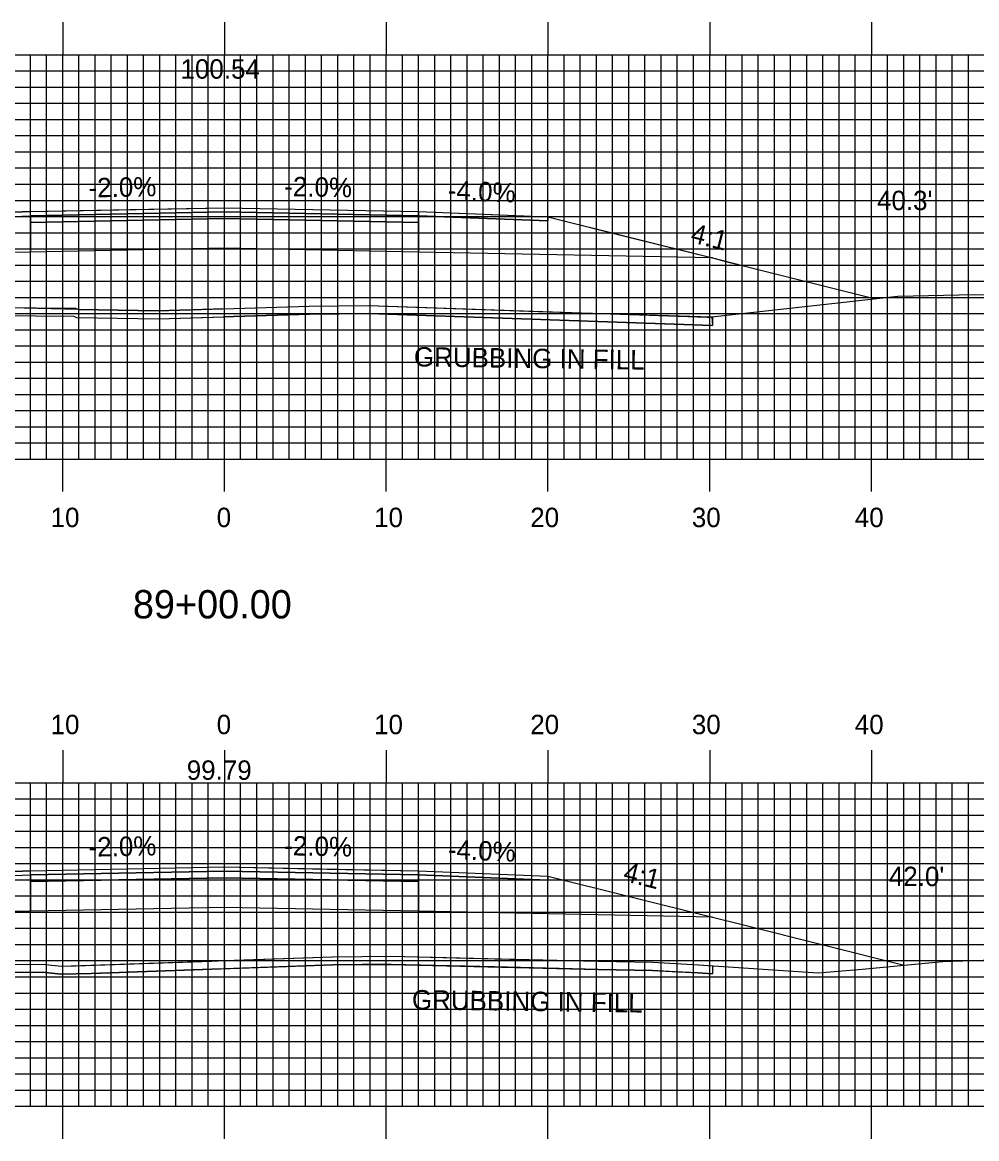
# Model space of a CAD drawing. Extents: x 1764152 to 1764495, y 442591 to 442811.
# Drawn here: x 1764305.3 to 1764364.3, y 442686.7 to 442755.7 of the extents above; entities that cross this region are included whole.
import ezdxf

# ---------------------------------------------------------------- set-up
doc = ezdxf.new("R2010")
doc.units = 0
for name, color, linetype in [('ANNOTATION', 7, 'Continuous'), ('D_Roadway_Centerline', 7, 'Continuous'), ('D_Roadway_Centerline_Text', 7, 'Continuous'), ('D_Roadway_Edge_Shoulder', 7, 'Continuous'), ('D_Roadway_Edge_TW', 7, 'Continuous'), ('D_Roadway_Pavement', 7, 'Continuous'), ('D_Roadway_SlopeLines', 7, 'Continuous'), ('D_Roadway_SubGrade', 7, 'Continuous'), ('D_Text_Standard', 7, 'Continuous'), ('GRUBBING IN FILL', 7, 'Continuous'), ('H_V ANNOTATION', 7, 'Continuous'), ('MAJOR', 7, 'Continuous'), ('MINOR', 7, 'Continuous'), ('S_Roadway_Centerline', 7, 'Continuous')]:
    doc.layers.add(name, color=color, linetype=linetype)

msp = doc.modelspace()

# ---------------------------------------------------------------- linework, layer by layer
at = {"layer": 'D_Roadway_Centerline'}
for points in [[(1764297.833, 442743.646), (1764305.832, 442743.966), (1764305.837, 442743.966), (1764311.976, 442744.089), (1764317.827, 442744.206), (1764317.832, 442744.206), (1764329.827, 442743.966), (1764329.832, 442743.966), (1764334.355, 442743.785), (1764337.829, 442743.646), (1764337.831, 442743.646), (1764343.157, 442742.315), (1764348.003, 442741.103), (1764348.006, 442741.102), (1764348.84, 442740.894), (1764349.832, 442740.646), (1764349.834, 442740.646), (1764358.085, 442738.582)], [(1764279.726, 442698.369), (1764287.655, 442700.352), (1764287.658, 442700.352), (1764297.83, 442702.896), (1764297.831, 442702.896), (1764305.828, 442703.216), (1764305.832, 442703.216), (1764305.837, 442703.216), (1764317.832, 442703.456), (1764317.837, 442703.456), (1764324.189, 442703.329), (1764329.827, 442703.216), (1764329.832, 442703.216), (1764337.832, 442702.896), (1764348.003, 442700.353), (1764348.006, 442700.352), (1764349.832, 442699.896), (1764359.855, 442697.39), (1764359.858, 442697.389)]]:
    msp.add_lwpolyline(points, dxfattribs=at)
at = {"layer": 'D_Roadway_Edge_Shoulder'}
for points in [[(1764305.832, 442743.966), (1764297.832, 442743.646), (1764297.832, 442743.396), (1764305.832, 442743.716)], [(1764329.832, 442743.966), (1764337.831, 442743.646), (1764337.831, 442743.396), (1764329.832, 442743.716)], [(1764305.832, 442703.216), (1764297.831, 442702.896), (1764297.831, 442702.646), (1764305.832, 442702.966)], [(1764329.832, 442703.216), (1764337.832, 442702.896), (1764337.832, 442702.646), (1764329.832, 442702.966)]]:
    msp.add_lwpolyline(points, close=True, dxfattribs=at)
at = {"layer": 'D_Roadway_Edge_TW'}
for points in [[(1764305.832, 442743.716), (1764305.832, 442743.966), (1764317.832, 442744.206), (1764329.832, 442743.966), (1764329.832, 442743.716), (1764317.832, 442743.956)], [(1764329.832, 442743.966), (1764329.832, 442743.966), (1764329.832, 442743.716), (1764329.832, 442743.716)], [(1764305.832, 442702.966), (1764305.832, 442703.216), (1764317.832, 442703.456), (1764329.832, 442703.216), (1764329.832, 442702.966), (1764317.832, 442703.206)], [(1764329.832, 442703.216), (1764329.832, 442703.216), (1764329.832, 442702.966), (1764329.832, 442702.966)]]:
    msp.add_lwpolyline(points, close=True, dxfattribs=at)
at = {"layer": 'D_Roadway_Pavement'}
for points in [[(1764305.832, 442743.299), (1764305.832, 442743.716), (1764317.832, 442743.956), (1764329.832, 442743.716), (1764329.832, 442743.299), (1764317.832, 442743.539)], [(1764329.832, 442743.716), (1764329.832, 442743.716), (1764329.832, 442743.299), (1764329.832, 442743.299)], [(1764305.832, 442702.549), (1764305.832, 442702.966), (1764317.832, 442703.206), (1764329.832, 442702.966), (1764329.832, 442702.549), (1764317.832, 442702.789)], [(1764329.832, 442702.966), (1764329.832, 442702.966), (1764329.832, 442702.549), (1764329.832, 442702.549)]]:
    msp.add_lwpolyline(points, close=True, dxfattribs=at)
for points in [[(1764329.832, 442743.716), (1764329.832, 442743.299)], [(1764329.832, 442743.716), (1764329.832, 442743.299)], [(1764329.832, 442743.716), (1764329.832, 442743.299)], [(1764329.832, 442702.966), (1764329.832, 442702.549)], [(1764329.832, 442702.966), (1764329.832, 442702.549)], [(1764329.832, 442702.966), (1764329.832, 442702.549)]]:
    msp.add_lwpolyline(points, dxfattribs=at)
at = {"layer": 'D_Roadway_SlopeLines'}
for points in [[(1764337.831, 442743.646), (1764348.006, 442741.102), (1764349.832, 442740.646), (1764358.085, 442738.582)], [(1764337.832, 442702.896), (1764348.005, 442700.352), (1764349.832, 442699.896), (1764359.858, 442697.389)]]:
    msp.add_lwpolyline(points, dxfattribs=at)
at = {"layer": 'D_Roadway_SubGrade'}
for points in [[(1764297.832, 442743.396), (1764305.832, 442743.716), (1764305.832, 442743.299), (1764305.832, 442741.466), (1764287.658, 442741.102), (1764297.832, 442743.646)], [(1764329.832, 442743.299), (1764329.832, 442743.716), (1764337.831, 442743.396), (1764337.831, 442743.646), (1764348.006, 442741.102), (1764329.832, 442741.466)], [(1764305.832, 442741.466), (1764305.832, 442743.299), (1764317.832, 442743.539), (1764329.832, 442743.299), (1764329.832, 442741.466), (1764317.832, 442741.706)], [(1764329.832, 442743.299), (1764329.832, 442743.299), (1764329.832, 442741.466), (1764329.832, 442741.466)], [(1764297.831, 442702.646), (1764305.832, 442702.966), (1764305.832, 442702.549), (1764305.832, 442700.716), (1764287.658, 442700.352), (1764297.831, 442702.896)], [(1764329.832, 442702.549), (1764329.832, 442702.966), (1764337.832, 442702.646), (1764337.832, 442702.896), (1764348.005, 442700.352), (1764329.832, 442700.716)], [(1764305.832, 442700.716), (1764305.832, 442702.549), (1764317.832, 442702.789), (1764329.832, 442702.549), (1764329.832, 442700.716), (1764317.832, 442700.956)], [(1764329.832, 442702.549), (1764329.832, 442702.549), (1764329.832, 442700.716), (1764329.832, 442700.716)]]:
    msp.add_lwpolyline(points, close=True, dxfattribs=at)
at = {"layer": 'GRUBBING IN FILL'}
for p, q in [((1764348.006, 442737.462), (1764348.006, 442736.93)), ((1764348.005, 442697.347), (1764348.005, 442696.846))]:
    msp.add_line(p, q, dxfattribs=at)
for points in [[(1764287.658, 442738.108), (1764289.607, 442738.031), (1764291.566, 442737.976), (1764297.792, 442737.756), (1764301.124, 442737.61), (1764301.59, 442737.589), (1764301.948, 442737.581), (1764303.753, 442737.543), (1764308.512, 442737.499), (1764308.687, 442737.428), (1764313.742, 442737.34), (1764317.832, 442737.463), (1764317.832, 442737.963), (1764313.739, 442737.84), (1764311.264, 442737.883), (1764308.789, 442737.926), (1764303.761, 442738.043), (1764293.972, 442738.424), (1764289.795, 442738.524), (1764287.658, 442738.609)], [(1764287.658, 442738.108), (1764289.607, 442738.031), (1764291.566, 442737.976), (1764297.792, 442737.756), (1764301.124, 442737.61), (1764301.59, 442737.589), (1764301.948, 442737.581), (1764303.753, 442737.543), (1764308.512, 442737.499), (1764308.687, 442737.428), (1764313.742, 442737.34), (1764317.832, 442737.463), (1764317.832, 442737.963), (1764313.739, 442737.84), (1764311.264, 442737.883), (1764308.789, 442737.926), (1764303.761, 442738.043), (1764293.972, 442738.424), (1764289.795, 442738.524), (1764287.658, 442738.609)], [(1764317.832, 442737.963), (1764318.404, 442737.981), (1764323.069, 442738.121), (1764326.754, 442738.164), (1764337.219, 442737.803), (1764347.961, 442737.457), (1764348.006, 442736.93), (1764337.377, 442737.297), (1764326.748, 442737.664), (1764324.914, 442737.642), (1764323.079, 442737.621), (1764318.411, 442737.481), (1764317.832, 442737.463)], [(1764317.832, 442737.963), (1764318.404, 442737.981), (1764323.069, 442738.121), (1764326.754, 442738.164), (1764337.219, 442737.803), (1764347.961, 442737.457), (1764348.006, 442736.93), (1764337.377, 442737.297), (1764326.748, 442737.664), (1764324.914, 442737.642), (1764323.079, 442737.621), (1764318.411, 442737.481), (1764317.832, 442737.463)], [(1764287.658, 442698.001), (1764291.965, 442697.77), (1764294.549, 442697.523), (1764297.109, 442697.506), (1764301.952, 442697.466), (1764306.795, 442697.426), (1764307.73, 442697.326), (1764308.647, 442697.353), (1764317.043, 442697.642), (1764317.832, 442697.669), (1764317.832, 442697.169), (1764317.056, 442697.142), (1764309.581, 442696.88), (1764307.711, 442696.825), (1764306.767, 442696.926), (1764301.937, 442696.966), (1764297.107, 442697.006), (1764294.9, 442697.009), (1764294.518, 442697.024), (1764294.342, 442697.036), (1764291.927, 442697.271), (1764287.658, 442697.5)], [(1764287.658, 442698.001), (1764291.965, 442697.77), (1764294.549, 442697.523), (1764297.109, 442697.506), (1764301.952, 442697.466), (1764306.795, 442697.426), (1764307.73, 442697.326), (1764308.647, 442697.353), (1764317.043, 442697.642), (1764317.832, 442697.669), (1764317.832, 442697.169), (1764317.056, 442697.142), (1764309.581, 442696.88), (1764307.711, 442696.825), (1764306.767, 442696.926), (1764301.937, 442696.966), (1764297.107, 442697.006), (1764294.9, 442697.009), (1764294.518, 442697.024), (1764294.342, 442697.036), (1764291.927, 442697.271), (1764287.658, 442697.5)], [(1764317.832, 442697.669), (1764324.52, 442697.904), (1764328.147, 442697.934), (1764334.545, 442697.781), (1764340.943, 442697.629), (1764344.313, 442697.563), (1764347.15, 442697.404), (1764348.005, 442697.347), (1764348.005, 442696.846), (1764347.119, 442696.905), (1764345.707, 442696.984), (1764344.294, 442697.063), (1764340.932, 442697.129), (1764334.537, 442697.281), (1764328.143, 442697.434), (1764326.337, 442697.419), (1764324.531, 442697.404), (1764317.832, 442697.169)], [(1764317.832, 442697.669), (1764324.52, 442697.904), (1764328.147, 442697.934), (1764334.545, 442697.781), (1764340.943, 442697.629), (1764344.313, 442697.563), (1764347.15, 442697.404), (1764348.005, 442697.347), (1764348.005, 442696.846), (1764347.119, 442696.905), (1764345.707, 442696.984), (1764344.294, 442697.063), (1764340.932, 442697.129), (1764334.537, 442697.281), (1764328.143, 442697.434), (1764326.337, 442697.419), (1764324.531, 442697.404), (1764317.832, 442697.169)]]:
    msp.add_lwpolyline(points, close=True, dxfattribs=at)
for points in [[(1764287.658, 442738.108), (1764289.779, 442738.024), (1764293.354, 442737.927), (1764293.959, 442737.924), (1764301.624, 442737.588), (1764303.753, 442737.543), (1764308.512, 442737.499), (1764308.687, 442737.428), (1764313.742, 442737.34), (1764323.079, 442737.621), (1764326.748, 442737.664), (1764348.006, 442736.93)], [(1764287.658, 442697.5), (1764291.927, 442697.271), (1764294.342, 442697.036), (1764294.693, 442697.013), (1764295.106, 442697.004), (1764297.107, 442697.006), (1764306.767, 442696.926), (1764307.711, 442696.825), (1764309.581, 442696.88), (1764324.531, 442697.404), (1764328.143, 442697.434), (1764340.932, 442697.129), (1764344.294, 442697.063), (1764347.119, 442696.905), (1764348.005, 442696.846)]]:
    msp.add_lwpolyline(points, dxfattribs=at)
at = {"layer": 'MAJOR'}
for p, q in [((1764307.832, 442755.669), (1764307.832, 442753.665)), ((1764317.832, 442755.669), (1764317.832, 442753.665)), ((1764327.832, 442755.669), (1764327.832, 442753.665)), ((1764337.832, 442755.669), (1764337.832, 442753.665)), ((1764347.832, 442755.669), (1764347.832, 442753.665)), ((1764357.832, 442755.669), (1764357.832, 442753.665)), ((1764177.832, 442753.665), (1764457.832, 442753.665)), ((1764177.832, 442753.665), (1764457.832, 442753.665)), ((1764307.832, 442728.665), (1764307.832, 442753.665)), ((1764317.832, 442728.665), (1764317.832, 442753.665)), ((1764327.832, 442728.665), (1764327.832, 442753.665)), ((1764337.832, 442728.665), (1764337.832, 442753.665)), ((1764347.832, 442728.665), (1764347.832, 442753.665)), ((1764357.832, 442728.665), (1764357.832, 442753.665)), ((1764177.832, 442748.665), (1764457.832, 442748.665)), ((1764177.832, 442743.665), (1764457.832, 442743.665)), ((1764177.832, 442738.665), (1764457.832, 442738.665)), ((1764177.832, 442733.665), (1764457.832, 442733.665)), ((1764177.832, 442728.665), (1764457.832, 442728.665)), ((1764177.832, 442728.665), (1764457.832, 442728.665)), ((1764307.832, 442726.661), (1764307.832, 442728.665)), ((1764317.832, 442726.661), (1764317.832, 442728.665)), ((1764327.832, 442726.661), (1764327.832, 442728.665)), ((1764337.832, 442726.661), (1764337.832, 442728.665)), ((1764347.832, 442726.661), (1764347.832, 442728.665)), ((1764357.832, 442726.661), (1764357.832, 442728.665)), ((1764307.832, 442710.669), (1764307.832, 442708.665)), ((1764317.832, 442710.669), (1764317.832, 442708.665)), ((1764327.832, 442710.669), (1764327.832, 442708.665)), ((1764337.832, 442710.669), (1764337.832, 442708.665)), ((1764347.832, 442710.669), (1764347.832, 442708.665)), ((1764357.832, 442710.669), (1764357.832, 442708.665)), ((1764177.832, 442708.665), (1764457.832, 442708.665)), ((1764177.832, 442708.665), (1764457.832, 442708.665)), ((1764307.832, 442688.665), (1764307.832, 442708.665)), ((1764317.832, 442688.665), (1764317.832, 442708.665)), ((1764327.832, 442688.665), (1764327.832, 442708.665)), ((1764337.832, 442688.665), (1764337.832, 442708.665)), ((1764347.832, 442688.665), (1764347.832, 442708.665)), ((1764357.832, 442688.665), (1764357.832, 442708.665)), ((1764177.832, 442703.665), (1764457.832, 442703.665)), ((1764177.832, 442698.665), (1764457.832, 442698.665)), ((1764177.832, 442693.665), (1764457.832, 442693.665)), ((1764177.832, 442688.665), (1764457.832, 442688.665)), ((1764177.832, 442688.665), (1764457.832, 442688.665)), ((1764307.832, 442686.661), (1764307.832, 442688.665)), ((1764317.832, 442686.661), (1764317.832, 442688.665)), ((1764327.832, 442686.661), (1764327.832, 442688.665)), ((1764337.832, 442686.661), (1764337.832, 442688.665)), ((1764347.832, 442686.661), (1764347.832, 442688.665)), ((1764357.832, 442686.661), (1764357.832, 442688.665))]:
    msp.add_line(p, q, dxfattribs=at)
at = {"layer": 'MINOR'}
for p, q in [((1764305.832, 442728.665), (1764305.832, 442753.665)), ((1764306.832, 442728.665), (1764306.832, 442753.665)), ((1764308.832, 442728.665), (1764308.832, 442753.665)), ((1764309.832, 442728.665), (1764309.832, 442753.665)), ((1764310.832, 442728.665), (1764310.832, 442753.665)), ((1764311.832, 442728.665), (1764311.832, 442753.665)), ((1764312.832, 442728.665), (1764312.832, 442753.665)), ((1764313.832, 442728.665), (1764313.832, 442753.665)), ((1764314.832, 442728.665), (1764314.832, 442753.665)), ((1764315.832, 442728.665), (1764315.832, 442753.665)), ((1764316.832, 442728.665), (1764316.832, 442753.665)), ((1764318.832, 442728.665), (1764318.832, 442753.665)), ((1764319.832, 442728.665), (1764319.832, 442753.665)), ((1764320.832, 442728.665), (1764320.832, 442753.665)), ((1764321.832, 442728.665), (1764321.832, 442753.665)), ((1764322.832, 442728.665), (1764322.832, 442753.665)), ((1764323.832, 442728.665), (1764323.832, 442753.665)), ((1764324.832, 442728.665), (1764324.832, 442753.665)), ((1764325.832, 442728.665), (1764325.832, 442753.665)), ((1764326.832, 442728.665), (1764326.832, 442753.665)), ((1764328.832, 442728.665), (1764328.832, 442753.665)), ((1764329.832, 442728.665), (1764329.832, 442753.665)), ((1764330.832, 442728.665), (1764330.832, 442753.665)), ((1764331.832, 442728.665), (1764331.832, 442753.665)), ((1764332.832, 442728.665), (1764332.832, 442753.665)), ((1764333.832, 442728.665), (1764333.832, 442753.665)), ((1764334.832, 442728.665), (1764334.832, 442753.665)), ((1764335.832, 442728.665), (1764335.832, 442753.665)), ((1764336.832, 442728.665), (1764336.832, 442753.665)), ((1764338.832, 442728.665), (1764338.832, 442753.665)), ((1764339.832, 442728.665), (1764339.832, 442753.665)), ((1764340.832, 442728.665), (1764340.832, 442753.665)), ((1764341.832, 442728.665), (1764341.832, 442753.665)), ((1764342.832, 442728.665), (1764342.832, 442753.665)), ((1764343.832, 442728.665), (1764343.832, 442753.665)), ((1764344.832, 442728.665), (1764344.832, 442753.665)), ((1764345.832, 442728.665), (1764345.832, 442753.665)), ((1764346.832, 442728.665), (1764346.832, 442753.665)), ((1764348.832, 442728.665), (1764348.832, 442753.665)), ((1764349.832, 442728.665), (1764349.832, 442753.665)), ((1764350.832, 442728.665), (1764350.832, 442753.665)), ((1764351.832, 442728.665), (1764351.832, 442753.665)), ((1764352.832, 442728.665), (1764352.832, 442753.665)), ((1764353.832, 442728.665), (1764353.832, 442753.665)), ((1764354.832, 442728.665), (1764354.832, 442753.665)), ((1764355.832, 442728.665), (1764355.832, 442753.665)), ((1764356.832, 442728.665), (1764356.832, 442753.665)), ((1764358.832, 442728.665), (1764358.832, 442753.665)), ((1764359.832, 442728.665), (1764359.832, 442753.665)), ((1764360.832, 442728.665), (1764360.832, 442753.665)), ((1764361.832, 442728.665), (1764361.832, 442753.665)), ((1764362.832, 442728.665), (1764362.832, 442753.665)), ((1764363.832, 442728.665), (1764363.832, 442753.665)), ((1764177.832, 442752.665), (1764457.832, 442752.665)), ((1764177.832, 442751.665), (1764457.832, 442751.665)), ((1764177.832, 442750.665), (1764457.832, 442750.665)), ((1764177.832, 442749.665), (1764457.832, 442749.665)), ((1764177.832, 442747.665), (1764457.832, 442747.665)), ((1764177.832, 442746.665), (1764457.832, 442746.665)), ((1764177.832, 442745.665), (1764457.832, 442745.665)), ((1764177.832, 442744.665), (1764457.832, 442744.665)), ((1764177.832, 442742.665), (1764457.832, 442742.665)), ((1764177.832, 442741.665), (1764457.832, 442741.665)), ((1764177.832, 442740.665), (1764457.832, 442740.665)), ((1764177.832, 442739.665), (1764457.832, 442739.665)), ((1764177.832, 442737.665), (1764457.832, 442737.665)), ((1764177.832, 442736.665), (1764457.832, 442736.665)), ((1764177.832, 442735.665), (1764457.832, 442735.665)), ((1764177.832, 442734.665), (1764457.832, 442734.665)), ((1764177.832, 442732.665), (1764457.832, 442732.665)), ((1764177.832, 442731.665), (1764457.832, 442731.665)), ((1764177.832, 442730.665), (1764457.832, 442730.665)), ((1764177.832, 442729.665), (1764457.832, 442729.665)), ((1764305.832, 442688.665), (1764305.832, 442708.665)), ((1764306.832, 442688.665), (1764306.832, 442708.665)), ((1764308.832, 442688.665), (1764308.832, 442708.665)), ((1764309.832, 442688.665), (1764309.832, 442708.665)), ((1764310.832, 442688.665), (1764310.832, 442708.665)), ((1764311.832, 442688.665), (1764311.832, 442708.665)), ((1764312.832, 442688.665), (1764312.832, 442708.665)), ((1764313.832, 442688.665), (1764313.832, 442708.665)), ((1764314.832, 442688.665), (1764314.832, 442708.665)), ((1764315.832, 442688.665), (1764315.832, 442708.665)), ((1764316.832, 442688.665), (1764316.832, 442708.665)), ((1764318.832, 442688.665), (1764318.832, 442708.665)), ((1764319.832, 442688.665), (1764319.832, 442708.665)), ((1764320.832, 442688.665), (1764320.832, 442708.665)), ((1764321.832, 442688.665), (1764321.832, 442708.665)), ((1764322.832, 442688.665), (1764322.832, 442708.665)), ((1764323.832, 442688.665), (1764323.832, 442708.665)), ((1764324.832, 442688.665), (1764324.832, 442708.665)), ((1764325.832, 442688.665), (1764325.832, 442708.665)), ((1764326.832, 442688.665), (1764326.832, 442708.665)), ((1764328.832, 442688.665), (1764328.832, 442708.665)), ((1764329.832, 442688.665), (1764329.832, 442708.665)), ((1764330.832, 442688.665), (1764330.832, 442708.665)), ((1764331.832, 442688.665), (1764331.832, 442708.665)), ((1764332.832, 442688.665), (1764332.832, 442708.665)), ((1764333.832, 442688.665), (1764333.832, 442708.665)), ((1764334.832, 442688.665), (1764334.832, 442708.665)), ((1764335.832, 442688.665), (1764335.832, 442708.665)), ((1764336.832, 442688.665), (1764336.832, 442708.665)), ((1764338.832, 442688.665), (1764338.832, 442708.665)), ((1764339.832, 442688.665), (1764339.832, 442708.665)), ((1764340.832, 442688.665), (1764340.832, 442708.665)), ((1764341.832, 442688.665), (1764341.832, 442708.665)), ((1764342.832, 442688.665), (1764342.832, 442708.665)), ((1764343.832, 442688.665), (1764343.832, 442708.665)), ((1764344.832, 442688.665), (1764344.832, 442708.665)), ((1764345.832, 442688.665), (1764345.832, 442708.665)), ((1764346.832, 442688.665), (1764346.832, 442708.665)), ((1764348.832, 442688.665), (1764348.832, 442708.665)), ((1764349.832, 442688.665), (1764349.832, 442708.665)), ((1764350.832, 442688.665), (1764350.832, 442708.665)), ((1764351.832, 442688.665), (1764351.832, 442708.665)), ((1764352.832, 442688.665), (1764352.832, 442708.665)), ((1764353.832, 442688.665), (1764353.832, 442708.665)), ((1764354.832, 442688.665), (1764354.832, 442708.665)), ((1764355.832, 442688.665), (1764355.832, 442708.665)), ((1764356.832, 442688.665), (1764356.832, 442708.665)), ((1764358.832, 442688.665), (1764358.832, 442708.665)), ((1764359.832, 442688.665), (1764359.832, 442708.665)), ((1764360.832, 442688.665), (1764360.832, 442708.665)), ((1764361.832, 442688.665), (1764361.832, 442708.665)), ((1764362.832, 442688.665), (1764362.832, 442708.665)), ((1764363.832, 442688.665), (1764363.832, 442708.665)), ((1764177.832, 442707.665), (1764457.832, 442707.665)), ((1764177.832, 442706.665), (1764457.832, 442706.665)), ((1764177.832, 442705.665), (1764457.832, 442705.665)), ((1764177.832, 442704.665), (1764457.832, 442704.665)), ((1764177.832, 442702.665), (1764457.832, 442702.665)), ((1764177.832, 442701.665), (1764457.832, 442701.665)), ((1764177.832, 442700.665), (1764457.832, 442700.665)), ((1764177.832, 442699.665), (1764457.832, 442699.665)), ((1764177.832, 442697.665), (1764457.832, 442697.665)), ((1764177.832, 442696.665), (1764457.832, 442696.665)), ((1764177.832, 442695.665), (1764457.832, 442695.665)), ((1764177.832, 442694.665), (1764457.832, 442694.665)), ((1764177.832, 442692.665), (1764457.832, 442692.665)), ((1764177.832, 442691.665), (1764457.832, 442691.665)), ((1764177.832, 442690.665), (1764457.832, 442690.665)), ((1764177.832, 442689.665), (1764457.832, 442689.665))]:
    msp.add_line(p, q, dxfattribs=at)
at = {"layer": 'S_Roadway_Centerline'}
for points in [[(1764253.294, 442739.495), (1764269.318, 442739.111), (1764282.737, 442738.728), (1764287.518, 442738.614), (1764289.795, 442738.524), (1764293.362, 442738.427), (1764293.972, 442738.424), (1764301.64, 442738.087), (1764303.761, 442738.043), (1764308.612, 442737.998), (1764308.789, 442737.926), (1764313.739, 442737.84), (1764323.069, 442738.121), (1764326.754, 442738.164), (1764347.684, 442737.441), (1764347.835, 442737.434), (1764347.961, 442737.457), (1764359.456, 442738.735), (1764364.202, 442738.837), (1764376.537, 442738.651)], [(1764255.595, 442698.38), (1764261.158, 442698.414), (1764273.951, 442698.559), (1764282.451, 442698.28), (1764291.965, 442697.77), (1764294.383, 442697.534), (1764294.715, 442697.513), (1764295.111, 442697.504), (1764297.109, 442697.506), (1764306.795, 442697.426), (1764307.73, 442697.326), (1764309.565, 442697.38), (1764324.52, 442697.904), (1764328.147, 442697.934), (1764340.943, 442697.629), (1764344.313, 442697.563), (1764347.15, 442697.404), (1764354.544, 442696.909), (1764357.266, 442697.148), (1764362.25, 442697.612), (1764368.48, 442697.827)]]:
    msp.add_lwpolyline(points, dxfattribs=at)

# ---------------------------------------------------------------- texts
at = {"layer": 'ANNOTATION'}
for s, rotation, p in [('-2.0%', 1.14571, (1764309.438, 442744.839)), ('-2.0%', 358.85423, (1764321.516, 442744.933)), ('-4.0%', 357.70924, (1764331.622, 442744.696)), ('4:1', 345.96175, (1764346.591, 442742.09)), ('-2.0%', 1.14571, (1764309.44, 442704.089)), ('-2.0%', 358.85416, (1764321.518, 442704.183)), ('-4.0%', 357.70947, (1764331.624, 442703.946)), ('4:1', 345.96054, (1764342.423, 442702.61))]:
    msp.add_text(s, height=1.2, rotation=rotation, dxfattribs=at).set_placement(p)
at = {"layer": 'D_Roadway_Centerline'}
for s, p in [('C', (1764317.826, 442744.206)), ('L', (1764317.832, 442744.199)), ('C', (1764317.827, 442703.456)), ('L', (1764317.832, 442703.449))]:
    msp.add_text(s, height=0.0146, dxfattribs=at).set_placement(p)
at = {"layer": 'D_Roadway_Centerline_Text'}
for s, p in [('100.54', (1764315.113, 442752.185)), ('99.79', (1764315.499, 442708.844))]:
    msp.add_text(s, height=1.2, dxfattribs=at).set_placement(p)
at = {"layer": 'D_Text_Standard'}
for s, p in [("40.3'", (1764358.179, 442744.059)), ("42.0'", (1764358.91, 442702.273))]:
    msp.add_text(s, height=1.2, dxfattribs=at).set_placement(p)
at = {"layer": 'GRUBBING IN FILL'}
for p in [(1764329.538, 442734.4), (1764329.415, 442694.656)]:
    msp.add_text('GRUBBING IN FILL', height=1.2, rotation=359.19507, dxfattribs=at).set_placement(p)
at = {"layer": 'H_V ANNOTATION'}
for s, height, p in [('10', 1.2, (1764307.082, 442724.465)), ('0', 1.2, (1764317.35, 442724.465)), ('10', 1.2, (1764327.082, 442724.465)), ('20', 1.2, (1764336.74, 442724.465)), ('30', 1.2, (1764346.729, 442724.465)), ('40', 1.2, (1764356.804, 442724.465)), ('89+00.00', 1.75, (1764312.167, 442718.821)), ('10', 1.2, (1764307.082, 442711.665)), ('0', 1.2, (1764317.35, 442711.665)), ('10', 1.2, (1764327.082, 442711.665)), ('20', 1.2, (1764336.74, 442711.665)), ('30', 1.2, (1764346.729, 442711.665)), ('40', 1.2, (1764356.804, 442711.665))]:
    msp.add_text(s, height=height, dxfattribs=at).set_placement(p)

doc.saveas('drawing.dxf')
